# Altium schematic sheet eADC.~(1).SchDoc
size A4; SheetNumber: 6; SheetTotal: 7
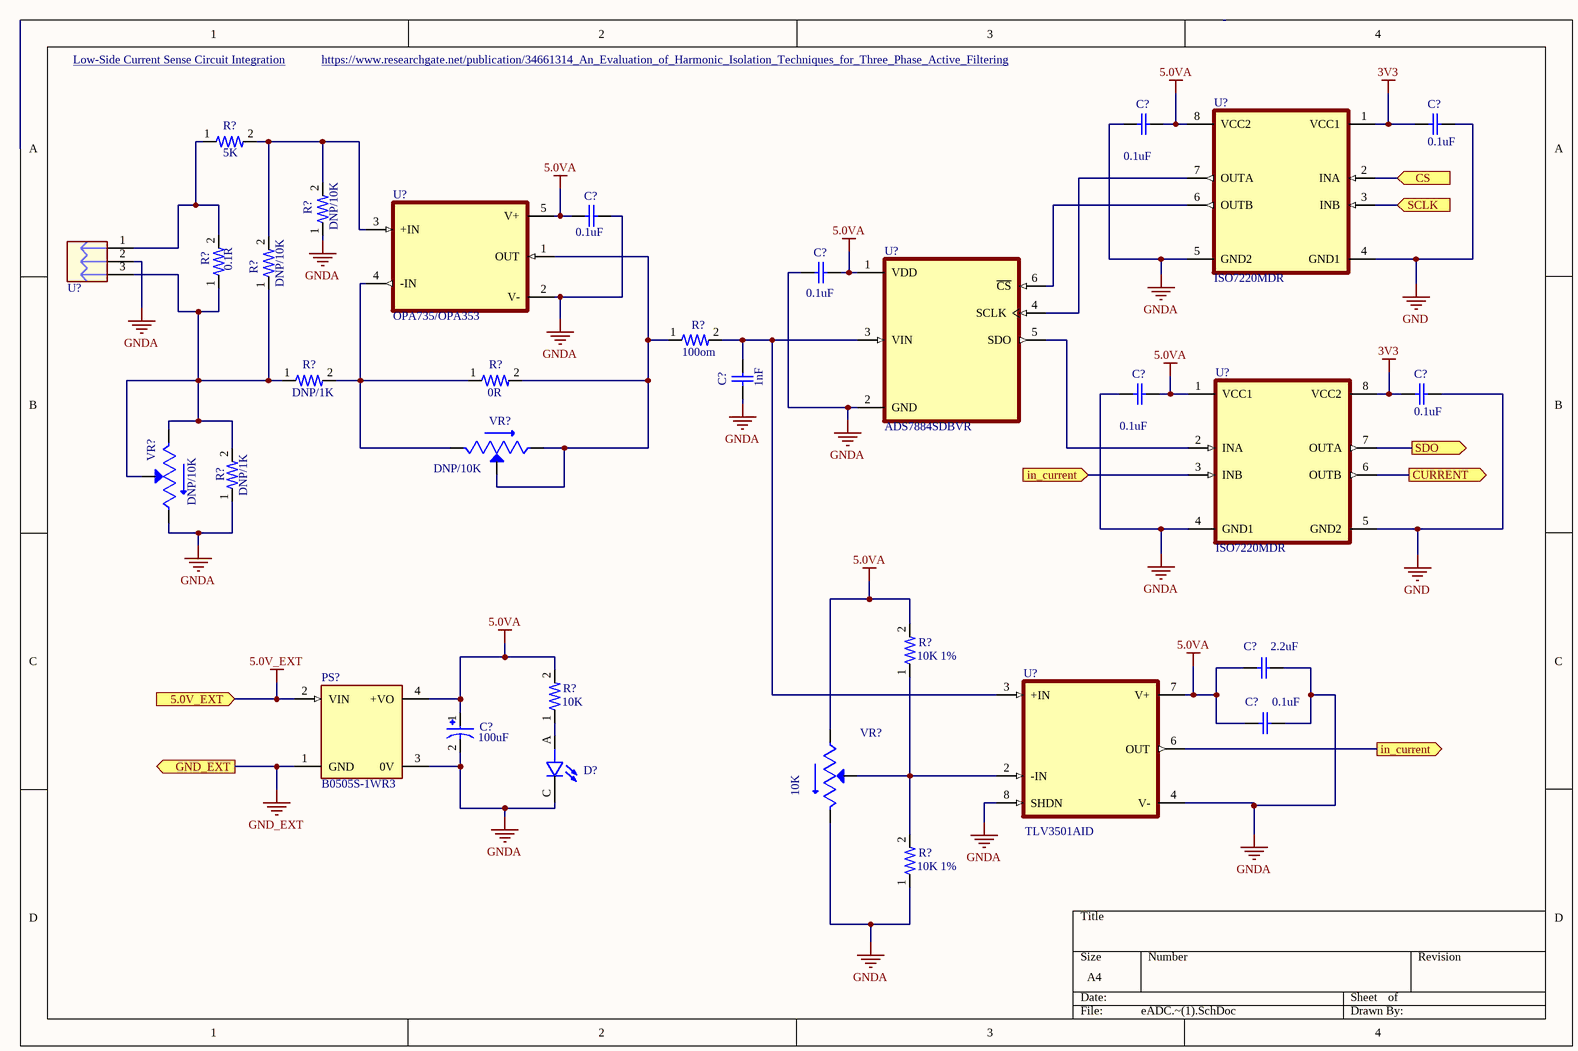
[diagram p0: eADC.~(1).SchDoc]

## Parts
(Parts that share a designator on the sheet are numbered #1, #2 ... from top to bottom, then left to right.)
C?#1  0.1uF  [CAP_0603]
C?#2  0.1uF  [CAP_0603]
C?#3  0.1uF  [CAP_0603]
C?#4  0.1uF  [CAP_0603]
C?#5  1nF  [CAP_0603]
C?#6  0.1uF  [CAP_0603]
C?#7  0.1uF  [CAP_0603]
C?#8  2.2uF  [CAP_0603]
C?#9  0.1uF  [CAP_0603]
C?#10  100uF  [CAP_TYPE_D]
D?  led_0603  [led_0603]  (value not drawn)
PS?  B0505S-1WR3  [B0505S-1WR3]
R?#1  5K  [RESC1608X50N]
R?#2  DNP/10K  [RESC1608X50N]
R?#3  0.1R  [RES_2512]
R?#4  DNP/10K  [RESC1608X50N]
R?#5  100om  [RESC1608X50N]
R?#6  DNP/1K  [RESC1608X50N]
R?#7  0R  [RESC1608X50N]
R?#8  DNP/1K  [RESC1608X50N]
R?#9  10K 1%  [RESC1608X50N]
R?#10  10K  [RESC1608X50N]
R?#11  10K 1%  [RESC1608X50N]
U?#1  ISO7220MDR  [ISO7220MDR]
U?#2  DG129-5.0-03P  [DG129-5.0-03P]  (value not drawn)
U?#3  OPA735/OPA353  [OPA735AIDBVR]
U?#4  ADS7884SDBVR  [ADS7884SDBVR]
U?#5  ISO7220MDR  [ISO7220MDR]
U?#6  TLV3501AID  [TLV3501AID]
VR?#1  DNP/10K  [TRIM_3296W-1-250]
VR?#2  DNP/10K  [TRIM_3296W-1-250]
VR?#3  10K  [TRIM_3296W-1-250]

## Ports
5.0V_EXT (in), CS (in), CURRENT (out), GND_EXT (out), in_current (in), in_current (out), SCLK (in), SDO (out)

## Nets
3V3: C?#2.2 C?#7.2 U?#1.1(VCC1) U?#5.8(VCC2)
5.0V_EXT: PS?.2(VIN) ; port 5.0V_EXT
5.0VA: C?#1.1 C?#3.2 C?#4.1 C?#6.1 C?#8.2 C?#9.2 C?#10.1 PS?.4(+VO) R?#9.2 R?#10.2 U?#1.8(VCC2) U?#3.5(V+) U?#4.1(VDD) U?#5.1(VCC1) U?#6.7(V+) VR?#3.1(CCW)
GND: C?#2.1 C?#7.1 U?#1.4(GND1) U?#5.5(GND2)
GND_EXT: PS?.1(GND) ; port GND_EXT
GNDA: C?#1.2 C?#3.1 C?#4.2 C?#5.2 C?#6.2 C?#8.1 C?#9.1 C?#10.2 D?.C PS?.3(0V) R?#2.1 R?#8.1 R?#11.1 U?#1.5(GND2) U?#2.2 U?#3.2(V-) U?#4.2(GND) U?#5.4(GND1) U?#6.4(V-) U?#6.8(SHDN) VR?#2.3(CW) VR?#3.3(CW)
CS: U?#1.2(INA) ; port CS
CURRENT: U?#5.6(OUTB) ; port CURRENT
in_current: U?#5.3(INB) U?#6.6(OUT) ; port in_current
SCLK: U?#1.3(INB) ; port SCLK
SDO: U?#5.7(OUTA) ; port SDO
NetC?#5_1: C?#5.1 R?#5.2 U?#4.3(VIN) U?#6.3(+IN)
NetD?_A: D?.A R?#10.1
NetR?#1_1: R?#1.1 R?#3.2 U?#2.1
NetR?#1_2: R?#1.2 R?#2.2 R?#4.2 U?#3.3(+IN)
NetR?#3_1: R?#3.1 R?#4.1 R?#6.1 R?#8.2 U?#2.3 VR?#2.1(CCW) VR?#2.2(WIPER)
NetR?#5_1: R?#5.1 R?#7.2 U?#3.1(OUT) VR?#1.2(WIPER) VR?#1.3(CW)
NetR?#6_2: R?#6.2 R?#7.1 U?#3.4(-IN) VR?#1.1(CCW)
NetR?#9_1: R?#9.1 R?#11.2 U?#6.2(-IN) VR?#3.2(WIPER)
NetU?#1_6: U?#1.6(OUTB) U?#4.6(~{CS})
NetU?#1_7: U?#1.7(OUTA) U?#4.4(SCLK)
NetU?#4_5: U?#4.5(SDO) U?#5.2(INA)

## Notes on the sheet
- Low-Side Current Sense Circuit Integration <https://www.ti.com/lit/an/sboa190/sboa190.pdf?ts=1649158428076&ref_url=https%253A%252F%252Fwww.google.com%252F>
- https://www.researchgate.net/publication/34661314_An_Evaluation_of_Harmonic_Isolation_Techniques_for_Three_Phase_Active_Filtering

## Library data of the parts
C?#1-C?#9 = CAP_0603
C?#10 = CAP_TYPE_D: MP: 25TQC15MV
D? = led_0603: LED Indication - Discrete 3.1V 0603 _1608 Metric_; MP: LTW-C191TLA; MF: Lite-On
PS? = B0505S-1WR3: Isolated Module DC DC Converter 1 Output 5V 200mA 4.5V - 5.5V Input; MF: Mornsun America, LLC
R?#1 R?#5 R?#7 R?#9-R?#11 = RES_0603: 1% 0.1W; MP: 1-2176071-4
R?#2 R?#4 R?#6 R?#8 = RES_0603: 1% 0.1W  10mA max; MP: 1-2176071-4
R?#3 = RES_2512: 2512 1% 1W; MP: 1-2176071-4
U?#1 U?#5 = ISO7220MDR: Dual-channel, 2/0, 150-Mbps digital isolator 8-SOIC -40 to 125; MF: Texas Instruments
U?#2 = DG129-5.0-03P: DG129-5.0-03P-14-00AH
U?#3 = OPA735AIDR
U?#4 = ADS7884SDBVR: 2.7V-5.5V, 10 Bit, 3MSPS, Serial ADC 6-SOT-23 -40 to 125; MF: Texas Instruments
VR?#1-VR?#3 = 3296W-1-250: 25 Ohms 0.5W, 1/2W PC Pins Through Hole Trimmer Potentiometer Cermet 25 Turn Top Adjustment; MF: Bourns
